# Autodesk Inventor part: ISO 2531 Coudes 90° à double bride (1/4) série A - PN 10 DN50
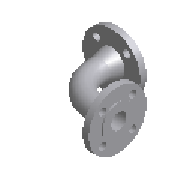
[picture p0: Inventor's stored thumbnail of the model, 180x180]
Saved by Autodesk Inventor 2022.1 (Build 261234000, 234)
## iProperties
Created: 2021-02
Part Number: ISO 2531 Coudes 90° à double bride (1/4) série A - PN 10 DN50
Material: Fonte, ductile
Description: Tuyaux en fonte ductile, raccords, accessoires et liaisons pour eau et gaz - Coudes à double bride 90° (1/4) - PN 10
Document SubType Name: Modeling
Standard: ISO 2531
Designer: Fabian
Standard Revision: Fifth edition 1998-08-15
Standards Organization: ISO
Language: fr-FR
Size Designation: DN50
Categories: <MemberInstance><Categories><Category DisplayName="Tubes et tuyaux" InternalName="4347fa0f-2144-441d-94cd-e3e15c92b736" Mnemonic="TUBEANDPIPE"><CategoryParamete
Density: 7.15 g/cm^3
Appearance: Fonte grise
IsCustomPart: 0
NAME: PIPING: ISO 2531 90 Deg Double Flanged Bend - PN 10
DATA: <meta><inlinegroups number="0" deflen="0"></inlinegroups><connections number="2"></connections><angles><a>1.5707963267949</a></angles></meta>
Author: Fabian
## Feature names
1. Revolution1
2. Sweep1
3. Revolution2
4. Extrusion1
5. Circular Pattern1
6. Extrusion2
7. Circular Pattern2
## Parameters: D = 165 mm, K1 = 125 mm, L2 = 19 mm, N3 = 84 mm, f1 = 3 mm, d11 = 99 mm, e = 7 mm, C7 = 19 mm, d0 = 165 mm, d1 = 84 mm, d2 = 7 mm, d3 = 99 mm, d4 = 3 mm, d5 = 15 deg, d7 = 66 mm, d15 = 90 deg, d9 = 7 mm, d10 = 3 mm, d13 = 99 mm, d14 = 165 mm, d16 = 84 mm, d17 = 66 mm, d18 = 7 mm, d19 = 0, d27 = 90 deg, d20 = 125 mm, d21 = 16 mm, d22 = 0, d24 = 360 deg, d25 = 125 mm, d26 = 16 mm, d28 = 0, d30 = 360 deg, d31 = 19 mm, d32 = 19 mm, d34 = 19 mm, d35 = 45 deg, d36 = 45 deg, d37 = 19 mm, d48 = 0, Size_Designation = 12.345 mm
